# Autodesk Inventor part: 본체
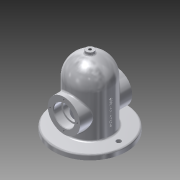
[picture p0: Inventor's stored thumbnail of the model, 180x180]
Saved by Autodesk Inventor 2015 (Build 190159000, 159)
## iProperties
Created: 2019-11
Part Number: 본체
Material: 알루미늄 6061
Document SubType Name: Modeling
Designer: now
Density: 2.7 g/cm^3
Appearance: 알루미늄 - 평지
Mass: 1106.12 g
Surface Area: 883.272 cm^2
Volume: 409.676 cm^3
Author: now
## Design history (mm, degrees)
sketch "스케치1"
  geometry: C1 r 70 at (0, 0); 1 further point
  constraints: 1 centre point, 1 coincident
  dimensions: "d0" = 140 diameter of C1
extrude "돌출1" new body sketch "스케치1" distance "d1" = 10; taper "d2" = 0 deg
sketch "스케치2"
  geometry: C1 r 70 at (0, 0) reference; C2 r 40 at (0, 0)
  constraints: 1 centre point, 1 coincident
  dimensions: "d3" = 80 diameter of C2
extrude "돌출2" join sketch "스케치2" distance "d4" = 120; taper "d5" = 0 deg
fillet "모깎기1" dims "d6" = 40
feature "쉘1" dims "d7" = 10
node "작업 평면1"
node "작업 평면2"
sketch "스케치8"
  geometry: C1 r 7.5 at (0, 0); 1 further point
  constraints: 1 centre point, 1 coincident
  dimensions: "d34" = 15 diameter of C1
extrude "돌출7" join sketch "스케치8" stored distance "d35" = 15; taper "d36" = 0 deg
sketch "스케치9"
  geometry: C1 r 7.5 at (0, 0) reference
hole "구멍2" sketch "스케치9" at (0, 0) diameter "d37" = 5.188; stored, may be unused: countersink angle "d41" = 90 deg, drill point angle "d43" = 118 deg; dims "d38" = 12, "d39" = 4, "d40" = 2, "d42" = 16
sketch "스케치10" dims "d44" = 110
  geometry: C1 r 40 at (0, 0) reference; C2 r 70 at (0, 0) reference; C3 r 4.5 at (55, 0); 2 further points
  constraints: 3 coincident, 2 horizontal alignment, 1 centre point, 2 other
  dimensions: "d45" = 9 diameter of C3
extrude "돌출8" cut sketch "스케치10" stored distance "d46" = 15; taper "d47" = 0 deg
fillet "모깎기2" dims "d48" = 3
fillet "모깎기4" dims "d50" = 3
node "작업 평면3"
sketch "스케치11"
  geometry: L1 (-70, 0)-(70, 0) reference; 3 further points
  constraints: 1 midpoint, 1 vertical alignment, 1 other
  dimensions: "d61" = 50 distance from line of L1 point (0, 50)
feature "엠보싱1" sketch "스케치11" dims "d62" = 0.5, "d63" = 0
node "작업 평면5"
  node "작업 평면4"
sketch "스케치12"
  geometry: L1 (-70, 0)-(70, 0) reference; C1 r 31 at (0, 50); 2 further points
  constraints: 1 centre point, 1 midpoint, 1 vertical alignment
  dimensions: "d66" = 62 diameter of C1; "d67" = 50 distance from line of L1 C1.centre
extrude "돌출9" join sketch "스케치12" stored distance "d68" = 15; taper "d69" = 0 deg
sketch "스케치13"
  geometry: C1 r 31 at (0, 0) reference; C2 r 20 at (0, 0); 1 further point
  constraints: 1 centre point, 1 coincident
  dimensions: "d70" = 40 diameter of C2
extrude "돌출10" cut sketch "스케치13" distance "d71" = 15; taper "d72" = 0 deg
sketch "스케치14"
  geometry: C1 r 20 at (0, 0) reference; C2 r 16.5 at (0, 0); 1 further point
  constraints: 1 centre point, 1 coincident
  dimensions: "d73" = 33 diameter of C2
extrude "돌출11" cut sketch "스케치14" stored distance "d74" = 15; taper "d75" = 0 deg
fillet "모깎기5" dims "d76" = 0.3
sketch "스케치15" dims "d77" = 52
  geometry: C1 r 20 at (0, 0) reference; C2 r 31 at (0, 0) reference; 3 further points
  constraints: 2 horizontal alignment, 1 coincident, 2 other
hole "구멍3" sketch "스케치15" at (26, 0) diameter "d78" = 3.242; stored, may be unused: countersink angle "d82" = 90 deg, drill point angle "d84" = 118 deg; dims "d79" = 8, "d80" = 4, "d81" = 2, "d83" = 10
chamfer "모따기3" distance "d88" = 1; stored, may be unused: second distance "d89" = 2, angle "d90" = 45 deg
fillet "모깎기6" dims "d91" = 0.3
fillet "모깎기7" dims "d92" = 3
fillet "모깎기8" dims "d93" = 3
node "솔리드1"
mirror "대칭4"
mirror "대칭7"
pattern_circular "원형 패턴3" dims angle "d86" = 360 deg
mirror "대칭8"
other parameters: "d33" = 135, "d64" = -5, "d65" = -45
